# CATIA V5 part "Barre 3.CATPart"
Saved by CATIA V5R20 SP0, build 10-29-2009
Part number: Barre 3
Bounding box of the stored display mesh (mm): x -169.738 to 9.99, y -449.99 to -371.866, z 10 to 20
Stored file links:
  C:\Users\Matthieu\Desktop\IFMA\Cours 2A\Thinkmotion\Projet_IAO_714_Matthieu_Perrusset\Barre 3.CATPart
  C:\Users\Matthieu\Desktop\IFMA\Cours 2A\Thinkmotion\Ass_skl_IAO.CATProduct
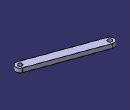
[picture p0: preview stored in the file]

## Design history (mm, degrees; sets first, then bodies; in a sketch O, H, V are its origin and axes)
AxisSystem1: origin (0, 0, 0), X (1, 0, 0), Y (0, 1, 0), Z (0, 0, 1)
Set1
  Line1 "Barre_3": linked copy from another document
  Line2 "Axe_Pivot_B": linked copy from another document
  Line3 "Axe_Pivot_b3b2": linked copy from another document
Body1 (main body)
  Plane1 "Plan_Ref": stored without definition
  Sketch1 on Plane1, origin (0, 0, 0), H (1, 0, 0), V (0, 1, 0)
    line L1 (-3.4202, -449.3969) -> (-163.1679, -391.2535)
    arc A1 centre (-159.7477, -381.8566) radius 10 from (-163.1679, -391.2535) to (-156.3275, -372.4596) cw
    point P3 (-159.7477, -381.8566)
    line L2 (-156.3275, -372.4596) -> (3.4202, -430.6031)
    arc A2 centre (0, -440) radius 10 from (3.4202, -430.6031) to (-3.4202, -449.3969) cw
    point P6 (0, -440)
    reference projected line E1 (-159.7477, -381.8566) -> (0, -440) from Line1
    reference projected line E2 (-159.7477, -381.8566) -> (0, -440) from Line1
    reference projected point E3 (0, -440) from Line2
    reference projected point E4 (-159.7477, -381.8566) from Line3
    reference projected line E5 (-159.7477, -381.8566) -> (0, -440) from Line1
    reference projected line E6 (-159.7477, -381.8566) -> (0, -440) from Line1
    circle A3 centre (-159.7477, -381.8566) radius 5
    circle A4 centre (0, -440) radius 5
    distance P3 A1 = 10
    distance E5 L1 = 10
    distance E6 L2 = 10
    distance P6 A2 = 10
    distance P3 A3 = 5
    distance P6 A4 = 5
    parallelism: L2 L1, E1 L1, E2 L2
    coincidence: E3 P6, P3 E4
  Pad1: profile Sketch1, direction (0, 0, 1), length 10, opposite side length -20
